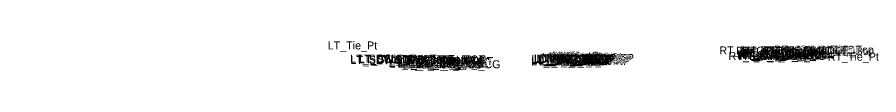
# Model space of a CAD drawing. Extents: x -26 to 4229, y -10 to 9523.
# Drawn here: x 2000 to 2215.4, y 9499.4 to 9506.9 of the extents above; entities that cross this region are included whole.
import ezdxf

# ---------------------------------------------------------------- set-up
doc = ezdxf.new("R2010")
doc.units = 0
doc.layers.add('Default', color=7, linetype='Continuous')

msp = doc.modelspace()

# ---------------------------------------------------------------- texts
at = {"layer": 'Default'}
for s, height, p in [('LT_Tie_Pt', 2, (2077.63, 9504.76)), ('RT_Sub_Trench_Out_DLT', 2, (2175.52, 9503.5)), ('RT_Sub_OEOT_CG', 2, (2177.82, 9502.15)), ('RT_CG_Top_Face', 2, (2179.71, 9503.46)), ('RT_CG1_Shelf_Out', 2, (2180, 9502.48)), ('RT_CG_Bot_IE', 2, (2180.37, 9502.4)), ('RT_PV2_OEOT', 2, (2180.63, 9502.74)), ('RT_PV3_OEOT', 2, (2180.63, 9502.49)), ('RT_CG_Top_Gut', 2, (2180.69, 9502.96)), ('RT_PV1_OEOT', 2, (2181.19, 9502.99)), ('RT_CG_Top_BOC', 2, (2181.24, 9503.46)), ('RT_CG_Bot_BOC', 2, (2181.27, 9502.47)), ('RT_Sub_OEOP', 2, (2183.81, 9502.24)), ('RT_SDWK_In_Top', 2, (2185.81, 9503.57)), ('RT_SDWK_In_Bot', 2, (2185.84, 9503.24)), ('RT_SDWK_Out_Top', 2, (2189.19, 9503.67)), ('RT_SDWK_Out_Bot', 2, (2189.22, 9503.34)), ('RT_Shld_O', 2, (2195.54, 9503.66)), ('CSLP_Pnt', 2, (2197.87, 9503.7)), ('LT_SDWK_Out_Top', 2, (2083.24, 9501.46)), ('LT_SDWK_Out_Bot', 2, (2083.27, 9501.13)), ('LT_CSLP_Pnt', 2, (2085.17, 9501.49)), ('LT_Sub_Trench_Out_DLT', 2, (2085.48, 9501.29)), ('LT_SDWK_In_Top', 2, (2089.86, 9501.36)), ('LT_SDWK_In_Bot', 2, (2089.89, 9501.03)), ('LT_CG1_Shelf_Out', 2, (2093.05, 9500.22)), ('LT_CG_Top_Face', 2, (2094.76, 9501.25)), ('LT_CG_Top_BOC', 2, (2095.28, 9501.25)), ('LT_CG_Bot_BOC', 2, (2095.31, 9500.23)), ('LT_CG_Top_Gut', 2, (2095.74, 9500.75)), ('LT_Sub_OEOT_CG', 2, (2096.87, 9500.05)), ('LT_CG_Bot_IE', 2, (2099.41, 9500.3)), ('LT_Sub_OEOT', 2, (2099.58, 9500)), ('LT_PV2_OEOT', 2, (2099.67, 9500.63)), ('LT_PV3_OEOT', 2, (2099.67, 9500.38)), ('LT_PV1_OEOT', 2, (2100.24, 9500.88)), ('LT_Sub_OEEOP', 2, (2128.46, 9500.78)), ('LT_PV2_OEEOP', 2, (2128.56, 9501.4)), ('LT_PV3_OEEOP', 2, (2128.56, 9501.15)), ('LT_PV1_OEEOP', 2, (2129.12, 9501.53)), ('LT_PV2_IEEOP', 2, (2129.2, 9501.4)), ('LT_PV1_IEEOP', 2, (2129.77, 9501.53)), ('LT_PV2_PGL1', 2, (2130.13, 9501.4)), ('LT_PV3_PGL1', 2, (2130.13, 9501.15)), ('LT_PV2_PGL', 2, (2130.46, 9501.4)), ('LT_PV4_PGL', 2, (2130.46, 9500.78)), ('LT_PV1_PGL', 2, (2131.03, 9501.65)), ('MI_Face In', 2, (2131.15, 9501.82)), ('MI_Bot In', 2, (2132.13, 9501.65)), ('RT_Sub_OEEOP', 2, (2132.42, 9500.88)), ('RT_PV2_OEEOP', 2, (2132.51, 9501.51)), ('RT_PV3_OEEOP', 2, (2132.51, 9501.26)), ('MI_Top In', 2, (2132.86, 9502.07)), ('RT_PV1_OEEOP', 2, (2133.08, 9501.63)), ('RT_PV2_IEEOP', 2, (2133.16, 9501.51)), ('MI_Face Out', 2, (2133.51, 9501.92)), ('MI_Top Out', 2, (2133.72, 9502.17)), ('RT_PV1_IEEOP', 2, (2133.72, 9501.63)), ('RT_PV2_PGL1', 2, (2134.08, 9501.51)), ('RT_PV3_PGL1', 2, (2134.08, 9501.26)), ('MI_Crown', 2, (2134.32, 9502.2)), ('RT_PV2_PGL', 2, (2134.42, 9501.51)), ('RT_PV4_PGL', 2, (2134.42, 9500.88)), ('MI_Bot Out', 2, (2134.51, 9501.76)), ('RT_PV1_PGL', 2, (2134.98, 9501.76)), ('RT_Sub_OEOT', 2, (2180.53, 9502.11)), ('RT_Tie_Pt', 2, (2202.61, 9501.96)), ('-', 0.0001, (2000, 9500)), ('-', 0.0001, (2000, 9500)), ('-', 0.0001, (2000, 9500)), ('-', 0.0001, (2000, 9500)), ('-', 0.0001, (2000, 9500)), ('-', 0.0001, (2000, 9500)), ('-', 0.0001, (2000, 9500)), ('LT_Sub_OEOP', 2, (2096.35, 9499.96))]:
    msp.add_text(s, height=height, dxfattribs=at).set_placement(p)

doc.saveas('drawing.dxf')
